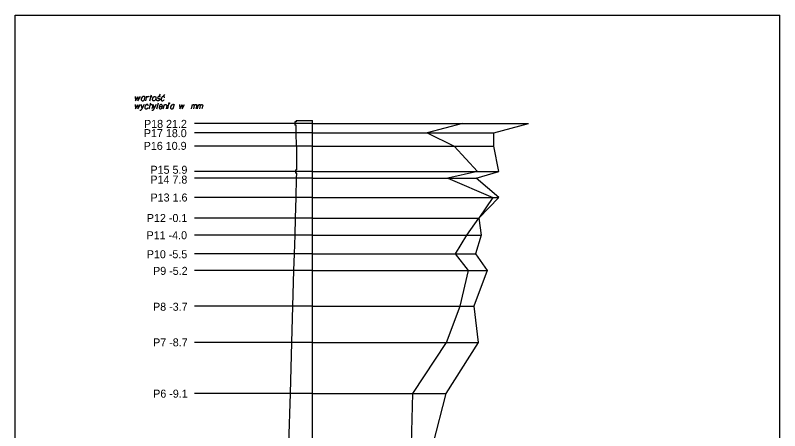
# Model space of a CAD drawing. Extents: x 138 to 6653, y -177 to 1520.
# Drawn here: x 318.59 to 339.59, y -45.34 to -33.92 of the extents above; entities that cross this region are included whole.
import ezdxf

# ---------------------------------------------------------------- set-up
doc = ezdxf.new("R2010")
doc.units = 0
for name, color, linetype in [('15 listopad 2008', 7, 'Continuous'), ('Ramka do drukowania', 7, 'Continuous'), ('Standart wykresów', 7, 'Continuous'), ('Wykresy 4 maj 2008', 7, 'Continuous')]:
    doc.layers.add(name, color=color, linetype=linetype)

msp = doc.modelspace()

# ---------------------------------------------------------------- linework, layer by layer
at = {"layer": '15 listopad 2008'}
msp.add_lwpolyline([(326.748, -52.61), (327.318, -51.164), (327.748, -49.788), (328.308, -48.421), (328.568, -47.063), (329.468, -45.704), (329.508, -44.313), (330.438, -42.911), (330.808, -41.918), (331.038, -40.937), (330.678, -40.478), (330.988, -39.961), (331.318, -39.493), (331.868, -38.925), (331.248, -38.4), (331.868, -38.212), (331.738, -37.514), (331.738, -37.151), (332.688, -36.895)], dxfattribs=at)
at = {"layer": 'Ramka do drukowania'}
for p, q in [((318.587, -63.621), (318.587, -33.921)), ((318.587, -33.921), (339.587, -33.921)), ((339.587, -63.621), (339.587, -33.921))]:
    msp.add_line(p, q, dxfattribs=at)
at = {"layer": 'Standart wykresów'}
for p, q in [((326.748, -36.895), (323.511, -36.895)), ((326.265, -36.853), (326.265, -36.895)), ((326.302, -36.853), (326.265, -36.853)), ((326.265, -36.895), (326.265, -36.937)), ((326.302, -36.937), (326.265, -36.937)), ((326.302, -36.811), (326.302, -36.853)), ((326.302, -36.811), (326.748, -36.811)), ((326.302, -37.151), (326.302, -36.937)), ((326.748, -56.895), (326.748, -36.811)), ((326.748, -37.151), (323.511, -37.151)), ((326.317, -37.514), (326.302, -37.151)), ((326.748, -37.514), (323.511, -37.514)), ((326.317, -37.514), (326.317, -38.168)), ((326.748, -38.212), (323.511, -38.212)), ((326.288, -38.168), (326.288, -38.212)), ((326.288, -38.168), (326.317, -38.168)), ((326.288, -38.212), (326.288, -38.256)), ((326.748, -38.4), (323.511, -38.4)), ((326.321, -38.256), (326.288, -38.256)), ((326.302, -38.925), (326.317, -38.4)), ((326.317, -38.4), (326.321, -38.256)), ((326.748, -38.925), (323.511, -38.925)), ((326.288, -39.493), (326.302, -38.925)), ((326.748, -39.493), (323.511, -39.493)), ((326.273, -39.961), (326.288, -39.493)), ((326.748, -39.961), (323.511, -39.961)), ((326.26, -40.478), (326.273, -39.961)), ((326.748, -40.478), (323.511, -40.478)), ((326.243, -40.937), (326.26, -40.478)), ((326.748, -40.937), (323.511, -40.937)), ((326.215, -41.918), (326.243, -40.937)), ((326.748, -41.918), (323.511, -41.918)), ((326.185, -42.911), (326.215, -41.918)), ((326.748, -42.911), (323.511, -42.911)), ((326.146, -44.313), (326.185, -42.911)), ((326.748, -44.313), (323.511, -44.313)), ((326.101, -45.704), (326.146, -44.313))]:
    msp.add_line(p, q, dxfattribs=at)
for points in [[(322.284, -36.271), (322.327, -36.105)], [(322.572, -36.093), (322.539, -36.13)], [(322.688, -36.095), (322.656, -36.131)], [(321.881, -36.152), (321.892, -36.271), (321.954, -36.163), (321.956, -36.271), (322.025, -36.15)], [(322.145, -36.161), (322.136, -36.155), (322.114, -36.155), (322.101, -36.157), (322.077, -36.171), (322.058, -36.194), (322.049, -36.219), (322.047, -36.232), (322.049, -36.242), (322.053, -36.252), (322.06, -36.262), (322.07, -36.269), (322.084, -36.271), (322.094, -36.27), (322.105, -36.269), (322.119, -36.261)], [(322.148, -36.151), (322.117, -36.271)], [(322.17, -36.271), (322.203, -36.147)], [(322.195, -36.177), (322.202, -36.172), (322.216, -36.161), (322.232, -36.155), (322.244, -36.151), (322.262, -36.147)], [(322.263, -36.494), (322.307, -36.328)], [(322.284, -36.151), (322.347, -36.151)], [(322.416, -36.151), (322.425, -36.151), (322.436, -36.156), (322.446, -36.171), (322.448, -36.177), (322.449, -36.184), (322.449, -36.189), (322.449, -36.208), (322.445, -36.222), (322.438, -36.237), (322.431, -36.25), (322.418, -36.262), (322.406, -36.271), (322.386, -36.271), (322.378, -36.269), (322.37, -36.262), (322.367, -36.256), (322.361, -36.24), (322.361, -36.216), (322.364, -36.208), (322.369, -36.191), (322.374, -36.182), (322.377, -36.177), (322.39, -36.163), (322.403, -36.155), (322.416, -36.151)], [(322.572, -36.171), (322.568, -36.161), (322.559, -36.155), (322.551, -36.152), (322.539, -36.151), (322.529, -36.152), (322.513, -36.16), (322.503, -36.171), (322.499, -36.18), (322.497, -36.19), (322.5, -36.197), (322.505, -36.201), (322.508, -36.202), (322.516, -36.205), (322.525, -36.206), (322.538, -36.208), (322.546, -36.211), (322.552, -36.219), (322.555, -36.228), (322.554, -36.24), (322.548, -36.25), (322.538, -36.262), (322.529, -36.267), (322.518, -36.27), (322.505, -36.271), (322.49, -36.27), (322.479, -36.265), (322.474, -36.258), (322.471, -36.249), (322.471, -36.24), (322.475, -36.232)], [(322.475, -36.494), (322.518, -36.328)], [(322.687, -36.186), (322.686, -36.171), (322.679, -36.16), (322.671, -36.155), (322.656, -36.152), (322.641, -36.152), (322.623, -36.164), (322.609, -36.184), (322.598, -36.203), (322.594, -36.218), (322.594, -36.24), (322.596, -36.248), (322.601, -36.258), (322.613, -36.269), (322.626, -36.271), (322.64, -36.27), (322.648, -36.267), (322.665, -36.256), (322.678, -36.233)], [(322.813, -36.328), (322.819, -36.328), (322.823, -36.33), (322.827, -36.335), (322.827, -36.342), (322.823, -36.347), (322.819, -36.35), (322.813, -36.35), (322.809, -36.347), (322.805, -36.342), (322.805, -36.335), (322.809, -36.33), (322.813, -36.328)], [(321.88, -36.375), (321.89, -36.494), (321.953, -36.385), (321.955, -36.494), (322.024, -36.372)], [(322.13, -36.372), (322.063, -36.494), (322.042, -36.529), (322.037, -36.532), (322.03, -36.534), (322.017, -36.537), (322.012, -36.537)], [(322.046, -36.373), (322.063, -36.494)], [(322.241, -36.409), (322.24, -36.393), (322.233, -36.383), (322.225, -36.377), (322.21, -36.375), (322.195, -36.375), (322.177, -36.386), (322.163, -36.406), (322.152, -36.426), (322.148, -36.44), (322.148, -36.462), (322.15, -36.47), (322.155, -36.481), (322.167, -36.491), (322.18, -36.494), (322.194, -36.492), (322.202, -36.49), (322.219, -36.478), (322.232, -36.456)], [(322.288, -36.398), (322.292, -36.393), (322.297, -36.385), (322.301, -36.381), (322.304, -36.379), (322.308, -36.376), (322.312, -36.375), (322.316, -36.373), (322.32, -36.372), (322.329, -36.372), (322.335, -36.373), (322.343, -36.376), (322.348, -36.379), (322.352, -36.383), (322.356, -36.388), (322.359, -36.392), (322.36, -36.394), (322.363, -36.4), (322.363, -36.403), (322.338, -36.494)], [(322.457, -36.372), (322.39, -36.494), (322.369, -36.529), (322.364, -36.532), (322.358, -36.534), (322.344, -36.537), (322.339, -36.537)], [(322.373, -36.373), (322.39, -36.494)], [(322.545, -36.424), (322.628, -36.424), (322.63, -36.411), (322.627, -36.4), (322.622, -36.388), (322.606, -36.376), (322.593, -36.375), (322.583, -36.377), (322.568, -36.385), (322.559, -36.394), (322.551, -36.409), (322.546, -36.419), (322.541, -36.441), (322.541, -36.456), (322.542, -36.468), (322.546, -36.478), (322.562, -36.492), (322.572, -36.494), (322.583, -36.492), (322.584, -36.492), (322.601, -36.485), (322.61, -36.475), (322.614, -36.469), (322.615, -36.468), (322.622, -36.456)], [(322.652, -36.494), (322.685, -36.373)], [(322.677, -36.402), (322.681, -36.396), (322.686, -36.388), (322.69, -36.384), (322.695, -36.379), (322.7, -36.376), (322.707, -36.373), (322.713, -36.372), (322.719, -36.372), (322.725, -36.373), (322.73, -36.376), (322.736, -36.379), (322.741, -36.383), (322.746, -36.388), (322.749, -36.392), (322.751, -36.397), (322.754, -36.403), (322.73, -36.494)], [(322.776, -36.494), (322.81, -36.367)], [(322.948, -36.384), (322.938, -36.377), (322.916, -36.377), (322.903, -36.38), (322.88, -36.393), (322.86, -36.417), (322.851, -36.441), (322.849, -36.455), (322.851, -36.465), (322.855, -36.474), (322.863, -36.485), (322.872, -36.491), (322.886, -36.494), (322.897, -36.492), (322.907, -36.491), (322.921, -36.483)], [(322.95, -36.373), (322.919, -36.494)], [(323.095, -36.375), (323.106, -36.494), (323.169, -36.385), (323.17, -36.494), (323.239, -36.372)], [(323.428, -36.494), (323.458, -36.375)], [(323.45, -36.406), (323.457, -36.392), (323.463, -36.384), (323.471, -36.379), (323.479, -36.375), (323.484, -36.372), (323.492, -36.372), (323.495, -36.373), (323.5, -36.379), (323.505, -36.385), (323.509, -36.397), (323.51, -36.403), (323.517, -36.392), (323.525, -36.384), (323.532, -36.379), (323.54, -36.375), (323.547, -36.372), (323.553, -36.372), (323.559, -36.373), (323.563, -36.379), (323.566, -36.385), (323.57, -36.397), (323.572, -36.403), (323.55, -36.494)], [(323.488, -36.494), (323.51, -36.403)], [(323.594, -36.494), (323.624, -36.375)], [(323.616, -36.406), (323.623, -36.392), (323.629, -36.384), (323.637, -36.379), (323.645, -36.375), (323.65, -36.372), (323.658, -36.372), (323.661, -36.373), (323.666, -36.379), (323.671, -36.385), (323.675, -36.397), (323.676, -36.403), (323.683, -36.392), (323.691, -36.384), (323.699, -36.379), (323.707, -36.375), (323.713, -36.372), (323.72, -36.372), (323.725, -36.373), (323.729, -36.379), (323.733, -36.385), (323.737, -36.397), (323.738, -36.403), (323.716, -36.494)], [(323.654, -36.494), (323.676, -36.403)]]:
    msp.add_lwpolyline(points, dxfattribs=at)
at = {"layer": 'Wykresy 4 maj 2008'}
for p, q in [((326.748, -36.895), (332.686, -36.895)), ((326.748, -37.151), (331.738, -37.151)), ((326.748, -37.514), (331.738, -37.514)), ((326.748, -38.212), (331.868, -38.212)), ((326.748, -38.4), (331.248, -38.4)), ((326.748, -38.925), (331.868, -38.925)), ((326.748, -39.493), (331.324, -39.493)), ((326.748, -39.961), (331.385, -39.961)), ((326.748, -40.478), (331.228, -40.478)), ((326.748, -40.937), (331.555, -40.937)), ((326.748, -41.918), (331.181, -41.918)), ((326.748, -42.911), (331.305, -42.911)), ((326.748, -44.313), (330.416, -44.313))]:
    msp.add_line(p, q, dxfattribs=at)
msp.add_lwpolyline([(330.874, -36.895), (329.903, -37.151), (330.648, -37.514), (331.281, -38.212), (330.469, -38.4), (331.71, -38.925), (331.324, -39.493), (331.385, -39.961), (331.228, -40.478), (331.555, -40.937), (331.181, -41.918), (331.305, -42.911), (330.416, -44.313), (330.058, -45.704), (329.309, -47.063), (328.638, -48.421), (328.154, -49.788), (327.31, -51.164), (326.748, -52.61)], dxfattribs=at)

# ---------------------------------------------------------------- texts
for s, p in [('P18 21.2', (322.124, -37.015)), ('P17 18.0', (322.119, -37.27)), ('P16 10.9', (322.115, -37.619)), ('P15 5.9', (322.301, -38.276)), ('P14 7.8', (322.299, -38.546)), ('P13 1.6', (322.303, -39.038)), ('P12 -0.1', (322.202, -39.602)), ('P11 -4.0', (322.194, -40.075)), ('P10 -5.5', (322.2, -40.597)), ('P9 -5.2', (322.373, -41.054)), ('P8 -3.7', (322.372, -42.04)), ('P7 -8.7', (322.374, -43.019)), ('P6 -9.1', (322.376, -44.428))]:
    msp.add_text(s, height=0.22, dxfattribs=at).set_placement(p)

doc.saveas('drawing.dxf')
